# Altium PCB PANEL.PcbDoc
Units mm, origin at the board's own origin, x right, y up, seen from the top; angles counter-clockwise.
Board outline 284.7 x 157.16 mm, 4 copper layers (TOP, GND, SIG, BOTTOM), stack 1.586 mm thick; 0 components, 0 nets, 24 pads, 0 vias.
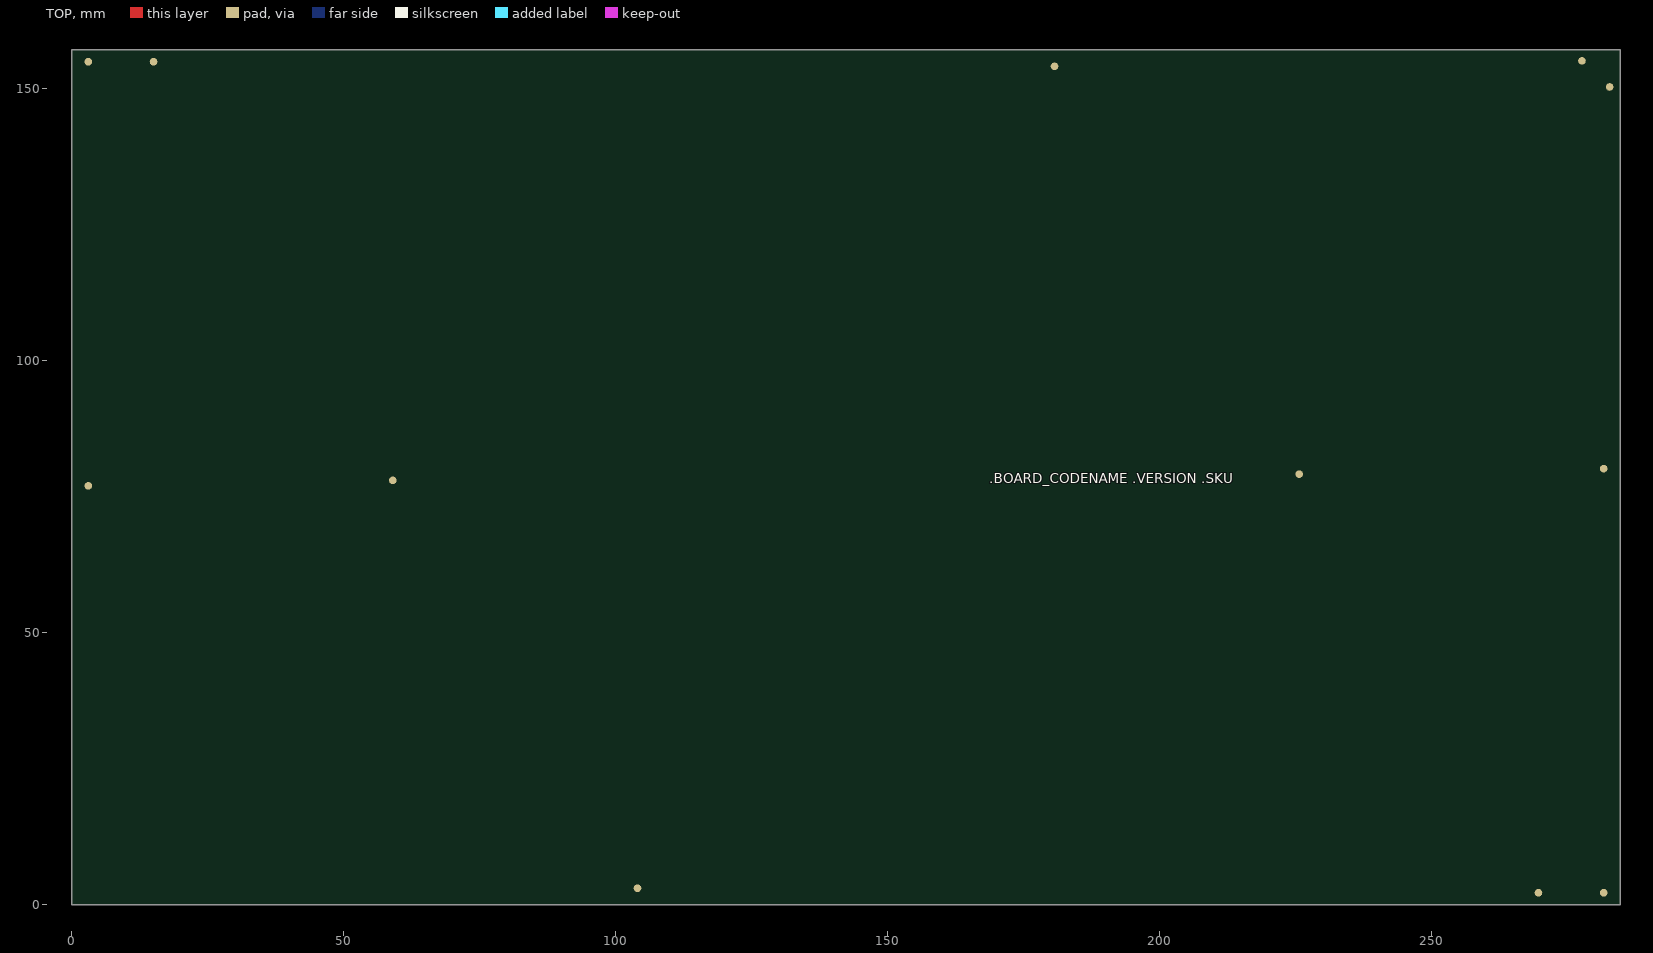
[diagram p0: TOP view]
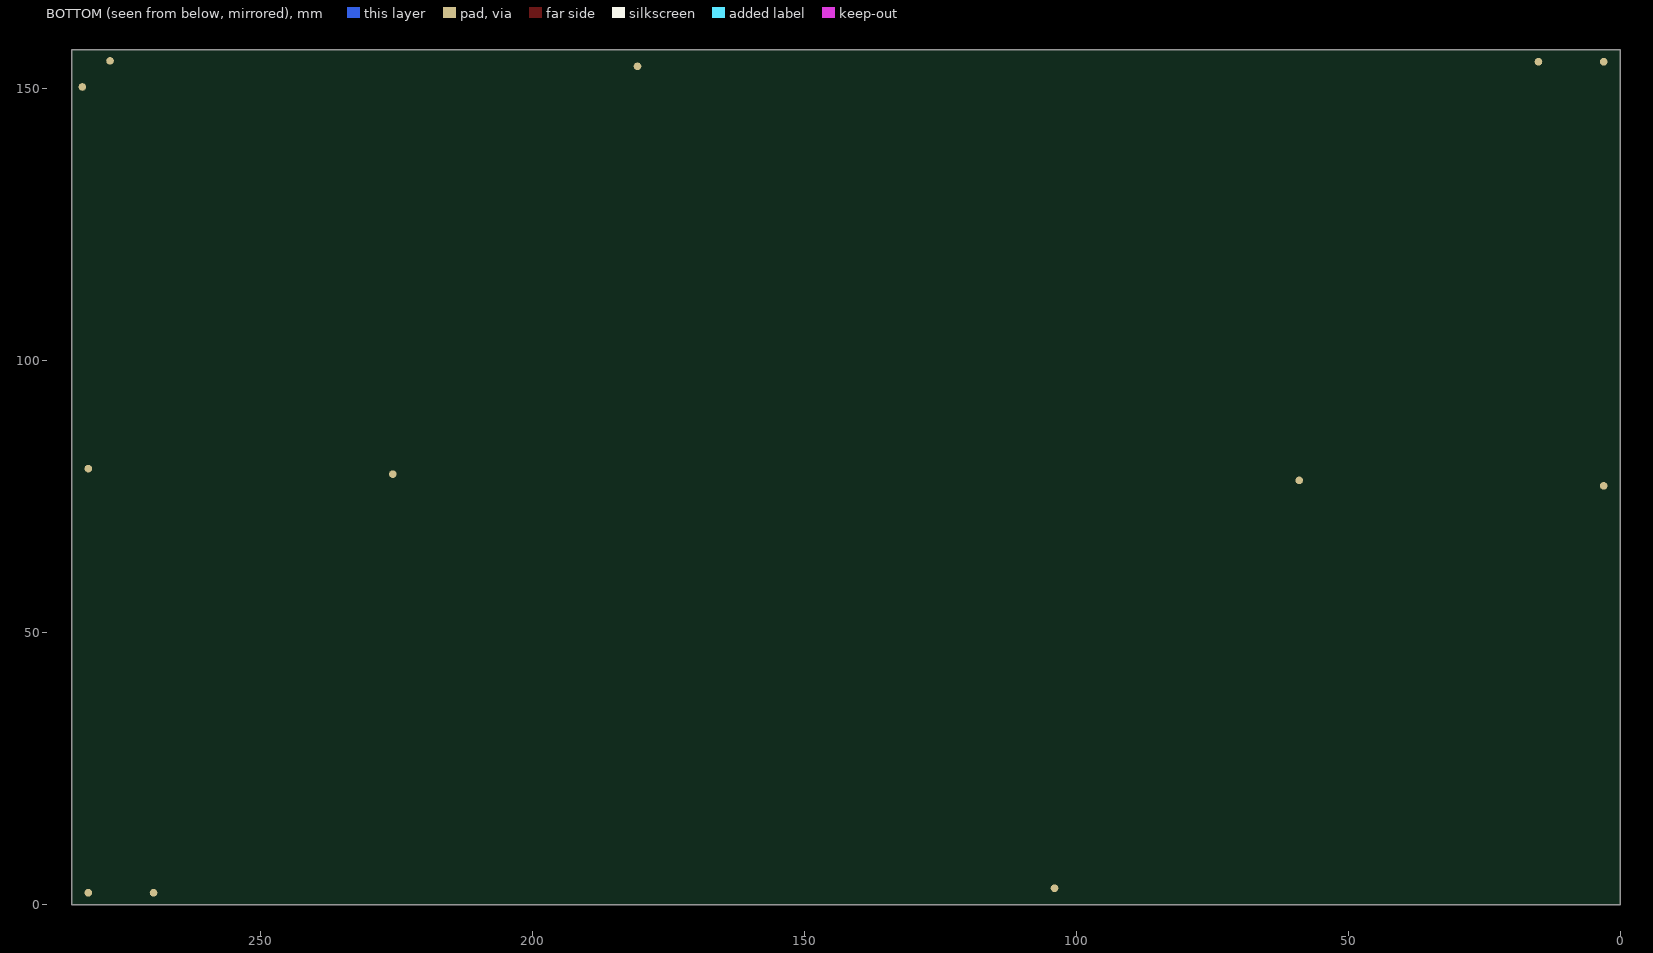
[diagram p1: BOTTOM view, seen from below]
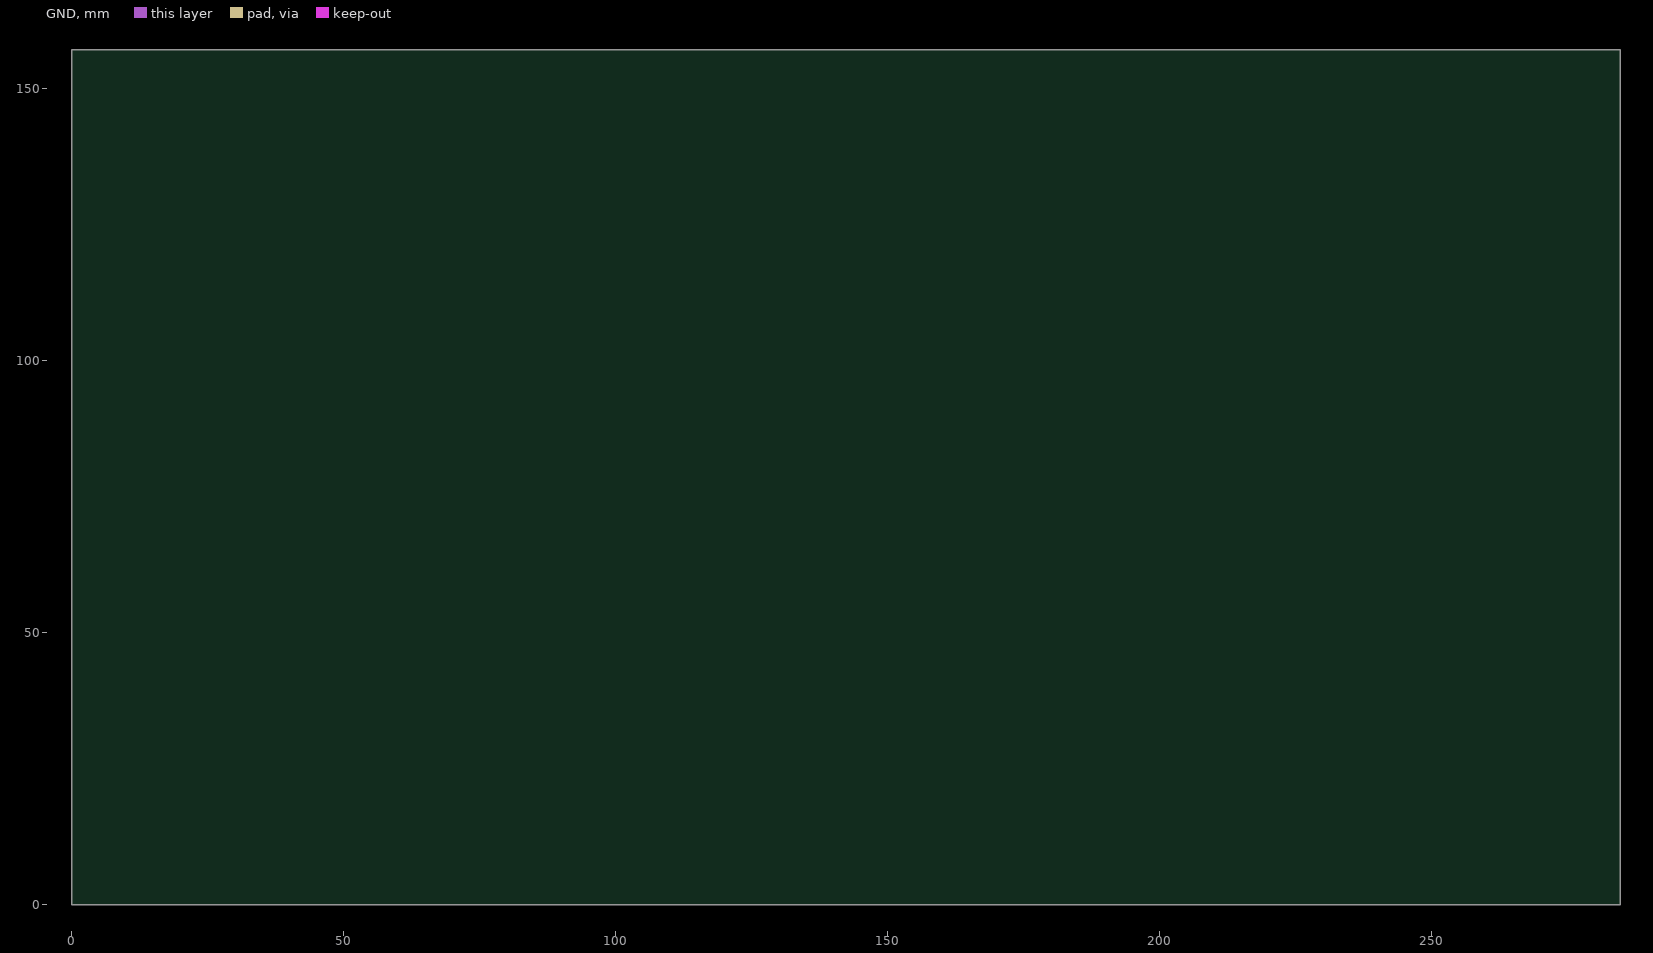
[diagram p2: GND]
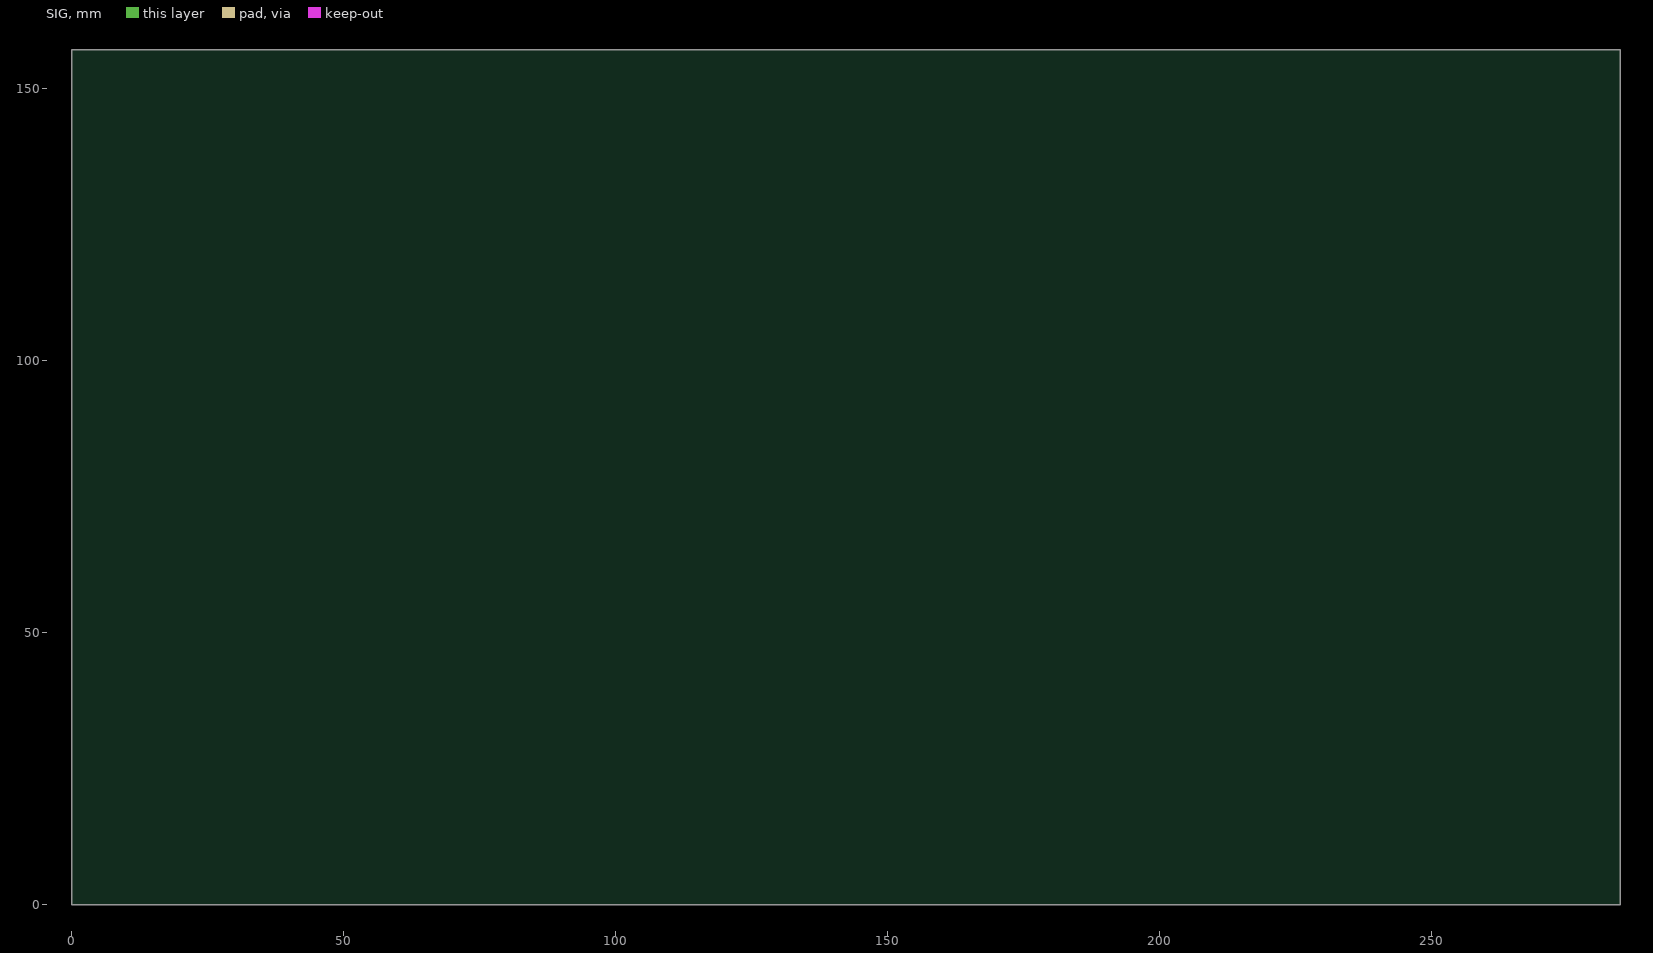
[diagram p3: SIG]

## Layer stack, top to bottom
Top Solder: solder mask 0.0102, Solder Resist, Dk 3.5
TOP: signal copper 0.018
Dielectric 1: prepreg 0.14, PP-014, Dk 4.2
GND: signal copper 0.035
Dielectric2: core 1.2, FR-4, Dk 4.8
SIG: signal copper 0.035
Dielectric3: prepreg 0.14, PP-014, Dk 4.2
BOTTOM: signal copper 0.018
Bottom Solder: solder mask 0.0102, Solder Resist, Dk 3.5

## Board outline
0,0 284.7,0 284.7,157.16 0,157.16

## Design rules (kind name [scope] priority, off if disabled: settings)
BoardOutlineClearance Silks [(OnLayer('Top Overlay') OR OnLayer('Bottom Overlay'))] p1: gap=0 ignorepadtopadclearanceinfootprint=FALSE
BoardOutlineClearance [All] p2: gap=0.3 ignorepadtopadclearanceinfootprint=FALSE
Clearance COPPER_0.3mm [All] p1: gap=0.127 ignorepadtopadclearanceinfootprint=FALSE except(0.3: Arc-Fill Arc-Poly Arc-Region Track-Fill Track-Poly Track-Region SMDPad-Fill SMDPad-Poly SMDPad-Region THPad-Fill THPad-Poly THPad-Region Via-Fill Via-Poly Via-Region Fill-Fill Fill-Poly Fill-Region Poly-Poly Poly-Region Region-Region)
Clearance "Generic clearance 0.127mm" [All] p2: gap=0.127 ignorepadtopadclearanceinfootprint=FALSE
ComponentClearance [All] p1: gap=0.2 collisioncheckmode=3 verticalgap=0 showdistances=TRUE
DiffPairsRouting USB [InDifferentialPairClass('USB')] p1: maxlimit=0.254 minlimit=0.15 mostfreqgap=0.254 toplayer_maxgap=0.15 toplayer_prefgap=0.15 toplayer_minwidth=0.15 toplayer_maxwidth=0.21 toplayer_prefwidth=0.2 midlayer2_mingap=0.24 midlayer2_maxgap=0.24 midlayer2_prefgap=0.24 midlayer2_minwidth=0.15 midlayer2_maxwidth=0.15 midlayer2_prefwidth=0.15 bottomlayer_maxgap=0.15 bottomlayer_prefgap=0.15 bottomlayer_minwidth=0.15 bottomlayer_maxwidth=0.21 bottomlayer_prefwidth=0.2 impedanceprofiledriven=TRUE impedanceprofileid={E6B00C31-4C8E-439C-824F-D2B2CDC26F9C} impedanceprofilevalue=90.000000 maxuncoupledlength=12.7
Height [All] p1: minheight=0 maxheight=30 prefheight=12.7
HoleSize [All] p1: absolutevalues=TRUE maxlimit=30 minlimit=0.3 maxpercent=80.000 minpercent=20.000
HoleToHoleClearance [All] p1: gap=0.25 allowstackedmicrovias=FALSE
MinimumAnnularRing [All] p1: minimumring=0.15
PlaneConnect [All] p1: pad.planeconnectstyle=Relief pad.reliefexpansion=0.508 pad.reliefentries=4 pad.reliefconductorwidth=0.254 pad.reliefairgap=0.254 via.planeconnectstyle=Direct via.reliefexpansion=0.508 via.reliefentries=4 via.reliefconductorwidth=0.254 via.reliefairgap=0.254
PolygonConnect [All] p1: thpad.connectstyle=Relief thpad.reliefconductorwidth=0.2 thpad.reliefentries=4 thpad.polygonreliefangle="90 Angle" thpad.airgapwidth=0.254 smdpad.connectstyle=Relief smdpad.reliefconductorwidth=0.2 smdpad.reliefentries=4 smdpad.polygonreliefangle="90 Angle" smdpad.airgapwidth=0.254 via.connectstyle=Direct via.reliefconductorwidth=0.254 via.reliefentries=4 via.polygonreliefangle="90 Angle" via.airgapwidth=0.254
RoutingVias StandardVias [All] p1: holewidth=0.3 width=0.6 viastyle="Through Hole" minholewidth=0.3 minwidth=0.6 maxholewidth=0.3 maxwidth=0.6
SMDToCorner [All] p1: distance=39370
SilkToSilkClearance [All] p1: silktosilkclearance=0.2
SilkToSolderMaskClearance [IsPad] p1: minsilkscreentomaskgap=0.15 clearancetoexposedcopper=TRUE
SolderMaskExpansion VIAtented [IsVia] p1: expansion=0.102 istentingtop=TRUE
SolderMaskExpansion [All] p2: expansion=0.05 istentingtop=FALSE
UnConnectedPin [All] p1:
UnRoutedNet [All] p1: checkbadconnections=TRUE
ViasUnderSMD [All] p1: allowed=FALSE
Width StandardTraces [All] p1: maxlimit=5 minlimit=0.127 preferedwidth=0.15
21 further rules are at their usual default settings.

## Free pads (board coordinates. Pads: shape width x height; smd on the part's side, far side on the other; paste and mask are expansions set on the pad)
  round 1.4 smd paste-5 mask+1: 21(3,77) 21(3,155) 21(15,155) 21(59,78) 21(104,3) 21(180.7,154.16) 21(225.7,79.16) 21(269.7,2.16) 21(277.7,155.16) 21(281.7,2.16) 21(281.7,80.16) 21(282.8,150.36)
  round 1.4 smd far side paste-5 mask+1: 21(3,77) 21(3,155) 21(15,155) 21(59,78) 21(104,3) 21(180.7,154.16) 21(225.7,79.16) 21(269.7,2.16) 21(277.7,155.16) 21(281.7,2.16) 21(281.7,80.16) 21(282.8,150.36)

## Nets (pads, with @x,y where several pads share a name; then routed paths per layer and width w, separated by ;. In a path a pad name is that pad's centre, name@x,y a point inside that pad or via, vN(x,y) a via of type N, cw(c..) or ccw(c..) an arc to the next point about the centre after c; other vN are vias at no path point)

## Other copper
TOP:
  text "TOP LAYER" at -54.1,76.984 h3
GND:
  text "LAYER 2" at -54.1,70.984 h3
SIG:
  text "LAYER 3" at -54.1,64.984 h3
BOTTOM:
  text "BOTTOM LAYER" at -54.1,58.984 h3

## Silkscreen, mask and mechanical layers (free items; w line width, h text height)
Top Overlay:
  text ".BOARD_CODENAME .VERSION .SKU" at 168.706,77.497 h1.8
  text "TOP SILK" at -54.1,40.984 h3
Bottom Overlay:
  text "BOTTOM SILK" at -54.1,34.984 h3
Top Paste:
  text "TOP PASTE" at -54.1,28.984 h3
Bottom Paste:
  text "BOTTOM PASTE" at -54.1,22.984 h3
Top Solder:
  text "TOP SOLDER" at -54.1,52.984 h3
Bottom Solder:
  text "BOTTOM SOLDER" at -54.1,46.984 h3
Route Tool Path:
  text "ROUTE TOOL PATH" at -54.1,10.984 h3
Board:
  the board outline again, w0.1
  text "OUTLINE" at -54.1,16.984 h3
SCORING:
  lines w0.1: 0,4.9 284.7,4.9 ; 0,73.68 284.7,73.68 ; 0,83.48 284.7,83.48 ; 0,152.253 284.7,152.253
  text "SCORING" at -54.1,5.2 h3

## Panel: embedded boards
"PCB.PcbDoc" at 279.7,83.58, 5 rows x 1 columns, spacing 55.34 x 80.58, rotation 90
"PCB.PcbDoc" at 5,73.58, 5 rows x 1 columns, spacing 55.34 x 80.58, rotation 270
